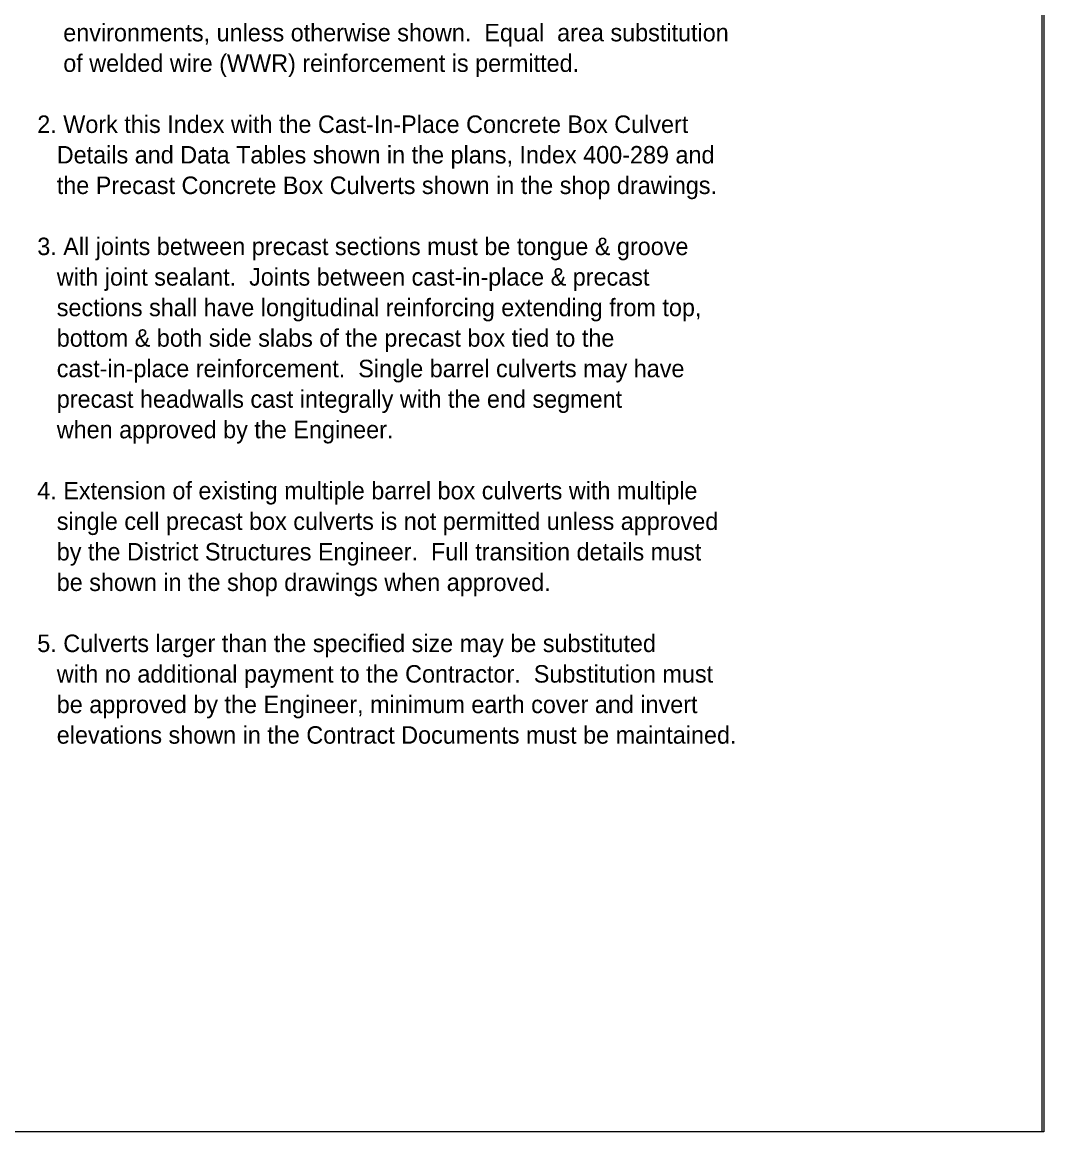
# Model space of a CAD drawing. Extents: x 0 to 123, y 0 to 78.
# Drawn here: x 87.86 to 123.2, y 0 to 38.37 of the extents above; entities that cross this region are included whole.
import ezdxf

# ---------------------------------------------------------------- set-up
doc = ezdxf.new("R2010")
doc.units = 0
for name, color, linetype in [('Dimension', 7, 'Continuous'), ('Miscellaneous1', 7, 'Continuous'), ('Patterning', 7, 'Continuous')]:
    doc.layers.add(name, color=color, linetype=linetype)

msp = doc.modelspace()

# ---------------------------------------------------------------- linework, layer by layer
at = {"layer": 'Miscellaneous1'}
msp.add_lwpolyline([(0, 77.856), (123.127, 77.856), (123.127, 0), (0, 0)], close=True, dxfattribs=at)
at = {"layer": 'Patterning'}
msp.add_lwpolyline([(0, 77.91), (123.2, 77.91), (123.2, 0), (0, 0)], close=True, dxfattribs=at)

# ---------------------------------------------------------------- texts
at = {"layer": 'Dimension'}
for s, p in [('    environments, unless otherwise shown.  Equal  area substitution', (88.385, 37.71)), ('    of welded wire (WWR) reinforcement is permitted.', (88.385, 36.654)), ('2. Work this Index with the Cast-In-Place Concrete Box Culvert ', (88.385, 34.542)), ('   Details and Data Tables shown in the plans, Index 400-289 and ', (88.385, 33.486)), ('   the Precast Concrete Box Culverts shown in the shop drawings.  ', (88.385, 32.43)), ('3. All joints between precast sections must be tongue & groove', (88.385, 30.318)), ('   with joint sealant.  Joints between cast-in-place & precast', (88.385, 29.262)), ('   sections shall have longitudinal reinforcing extending from top,', (88.385, 28.206)), ('   bottom & both side slabs of the precast box tied to the', (88.385, 27.15)), ('   cast-in-place reinforcement.  Single barrel culverts may have', (88.385, 26.094)), ('   precast headwalls cast integrally with the end segment', (88.385, 25.038)), ('   when approved by the Engineer.', (88.385, 23.982)), ('4. Extension of existing multiple barrel box culverts with multiple', (88.385, 21.87)), ('   single cell precast box culverts is not permitted unless approved', (88.385, 20.814)), ('   by the District Structures Engineer.  Full transition details must', (88.385, 19.758)), ('   be shown in the shop drawings when approved.', (88.385, 18.702)), ('5. Culverts larger than the specified size may be substituted', (88.385, 16.59)), ('   with no additional payment to the Contractor.  Substitution must', (88.385, 15.534)), ('   be approved by the Engineer, minimum earth cover and invert', (88.385, 14.478)), ('   elevations shown in the Contract Documents must be maintained.', (88.385, 13.422))]:
    msp.add_text(s, height=0.6048, dxfattribs=at).set_placement(p)

doc.saveas('drawing.dxf')
